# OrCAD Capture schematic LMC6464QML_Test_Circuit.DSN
size A; title: LMC6464QML Quad Micropower, Rail-to-Rail Input and Output; rev: 1.3; note: Datasheet: SNOSAR8A EVM: N/A
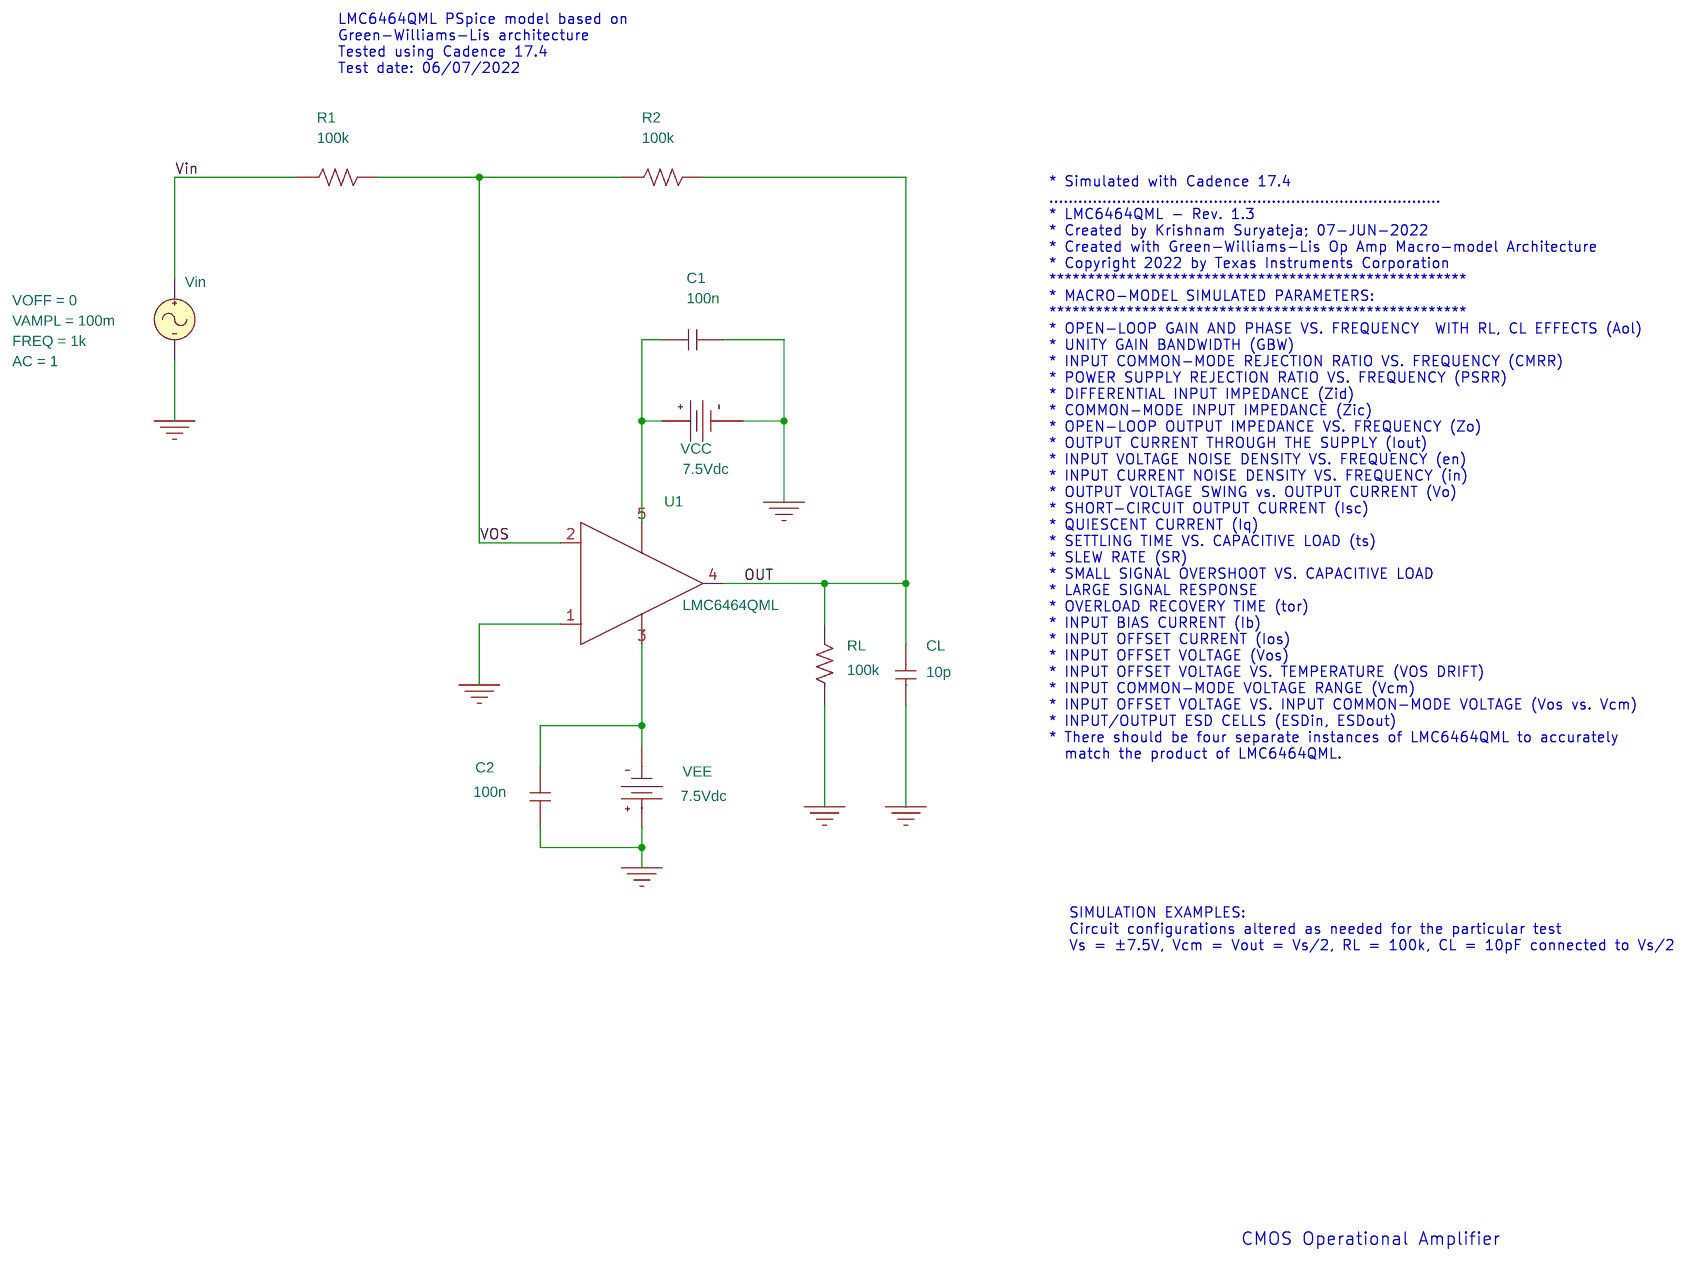
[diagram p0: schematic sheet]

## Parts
C1  100n  [cap196]
C2  100n  [cap196]
CL  10p  [cap196]
R1  100k  [AXRC05]
R2  100k  [AXRC05]
RL  100k  [AXRC05]
U1  LMC6464QML
VCC  VDC
VEE  VDC
Vin  VSIN

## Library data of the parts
C1 C2 CL = C
R1 R2 RL = R
U1 = LMC6464QML
VCC VEE = VDC: DC: 7.5Vdc
Vin = VSIN: AC: 1; FREQ: 1k; VAMPL: 100m; VOFF: 0

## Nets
Vin: R1.1 Vin.1(+)
0: C1.2 C2.1 CL.2 RL.1 U1.1(+) VCC.1(-) VEE.0(+) Vin.2(-)
OUT: CL.1 R2.2 RL.2 U1.4(OUT)
VOS: R1.2 R2.1 U1.2(-)
N27303: C1.1 U1.5(V+) VCC.0(+)
N27354: C2.2 U1.3(V-) VEE.1(-)

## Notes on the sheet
- LMC6464QML PSpice model based on
  Green-Williams-Lis architecture
  Tested using Cadence 17.4
  Test date: 06/07/2022
- * Simulated with Cadence 17.4
  .................................................................................
  * LMC6464QML - Rev. 1.3
  * Created by Krishnam Suryateja; 07-JUN-2022
  * Created with Green-Williams-Lis Op Amp Macro-model Architecture
  * Copyright 2022 by Texas Instruments Corporation
  ******************************************************
  * MACRO-MODEL SIMULATED PARAMETERS:
  ******************************************************
  * OPEN-LOOP GAIN AND PHASE VS. FREQUENCY  WITH RL, CL EFFECTS (Aol)
  * UNITY GAIN BANDWIDTH (GBW)
  * INPUT COMMON-MODE REJECTION RATIO VS. FREQUENCY (CMRR)
  * POWER SUPPLY REJECTION RATIO VS. FREQUENCY (PSRR)
  * DIFFERENTIAL INPUT IMPEDANCE (Zid)
  * COMMON-MODE INPUT IMPEDANCE (Zic)
  * OPEN-LOOP OUTPUT IMPEDANCE VS. FREQUENCY (Zo)
  * OUTPUT CURRENT THROUGH THE SUPPLY (Iout)
  * INPUT VOLTAGE NOISE DENSITY VS. FREQUENCY (en)
  * INPUT CURRENT NOISE DENSITY VS. FREQUENCY (in)
  * OUTPUT VOLTAGE SWING vs. OUTPUT CURRENT (Vo)
  * SHORT-CIRCUIT OUTPUT CURRENT (Isc)
  * QUIESCENT CURRENT (Iq)
  * SETTLING TIME VS. CAPACITIVE LOAD (ts)
  * SLEW RATE (SR)
  * SMALL SIGNAL OVERSHOOT VS. CAPACITIVE LOAD
  * LARGE SIGNAL RESPONSE
  * OVERLOAD RECOVERY TIME (tor)
  * INPUT BIAS CURRENT (Ib)
  * INPUT OFFSET CURRENT (Ios)
  * INPUT OFFSET VOLTAGE (Vos)
  * INPUT OFFSET VOLTAGE VS. TEMPERATURE (VOS DRIFT)
  * INPUT COMMON-MODE VOLTAGE RANGE (Vcm)
  * INPUT OFFSET VOLTAGE VS. INPUT COMMON-MODE VOLTAGE (Vos vs. Vcm)
  * INPUT/OUTPUT ESD CELLS (ESDin, ESDout)
  * There should be four separate instances of LMC6464QML to accurately
    match the product of LMC6464QML.
- SIMULATION EXAMPLES:
  Circuit configurations altered as needed for the particular test
  Vs = ±7.5V, Vcm = Vout = Vs/2, RL = 100k, CL = 10pF connected to Vs/2
- CMOS Operational Amplifier
